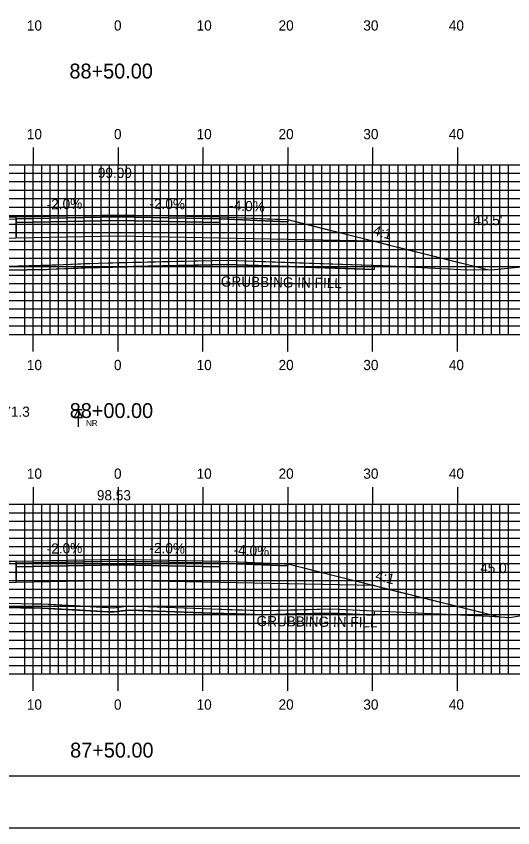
# Model space of a CAD drawing. Extents: x 1764152 to 1764495, y 442591 to 442811.
# Drawn here: x 1764305.8 to 1764364.3, y 442590.5 to 442686.2 of the extents above; entities that cross this region are included whole.
import ezdxf

# ---------------------------------------------------------------- set-up
doc = ezdxf.new("R2010")
doc.units = 0
for name, color, linetype in [('ANNOTATION', 7, 'Continuous'), ('BORDER', 7, 'Continuous'), ('BORING - NO REFUSAL', 7, 'Continuous'), ('D_Roadway_Centerline', 7, 'Continuous'), ('D_Roadway_Centerline_Text', 7, 'Continuous'), ('D_Roadway_Edge_Shoulder', 7, 'Continuous'), ('D_Roadway_Edge_TW', 7, 'Continuous'), ('D_Roadway_Pavement', 7, 'Continuous'), ('D_Roadway_SlopeLines', 7, 'Continuous'), ('D_Roadway_SubGrade', 7, 'Continuous'), ('D_Text_Standard', 7, 'Continuous'), ('GRUBBING IN FILL', 7, 'Continuous'), ('H_V ANNOTATION', 7, 'Continuous'), ('MAJOR', 7, 'Continuous'), ('MINOR', 7, 'Continuous'), ('PLOT BOUNDARY', 7, 'Continuous'), ('S_Roadway_Centerline', 7, 'Continuous')]:
    doc.layers.add(name, color=color, linetype=linetype)

msp = doc.modelspace()

# ---------------------------------------------------------------- linework, layer by layer
at = {"layer": 'BORDER'}
msp.add_lwpolyline([(1764168.232, 442596.665), (1764488.232, 442596.665), (1764488.232, 442806.665), (1764168.232, 442806.665)], close=True, dxfattribs=at)
at = {"layer": 'BORING - NO REFUSAL'}
for p, q in [((1764313.611, 442639.787), (1764312.652, 442639.787)), ((1764313.132, 442638.827), (1764313.132, 442637.768))]:
    msp.add_line(p, q, dxfattribs=at)
msp.add_lwpolyline([(1764313.132, 442639.787), (1764313.611, 442638.827), (1764312.652, 442638.827)], close=True, dxfattribs=at)
at = {"layer": 'D_Roadway_Centerline'}
for points in [[(1764280.078, 442657.758), (1764284.623, 442658.894), (1764287.657, 442659.653), (1764292.966, 442660.981), (1764297.813, 442662.192), (1764297.832, 442662.197), (1764297.847, 442662.198), (1764304.946, 442662.482), (1764305.832, 442662.517), (1764317.826, 442662.757), (1764317.831, 442662.757), (1764329.826, 442662.517), (1764329.832, 442662.517), (1764329.836, 442662.517), (1764336.402, 442662.254), (1764337.832, 442662.197), (1764339.339, 442661.82), (1764348.006, 442659.653), (1764349.62, 442659.25), (1764349.832, 442659.197), (1764351.315, 442658.826), (1764361.371, 442656.312)], [(1764279.768, 442617.12), (1764287.379, 442619.022), (1764287.658, 442619.092), (1764296.589, 442621.326), (1764297.831, 442621.636), (1764305.196, 442621.931), (1764305.832, 442621.956), (1764317.832, 442622.196), (1764329.832, 442621.956), (1764333.031, 442621.828), (1764337.448, 442621.652), (1764337.831, 442621.636), (1764341.569, 442620.702), (1764348.004, 442619.093), (1764348.006, 442619.092), (1764349.264, 442618.778), (1764349.831, 442618.636), (1764349.833, 442618.636), (1764350.364, 442618.503), (1764362.819, 442615.389)]]:
    msp.add_lwpolyline(points, dxfattribs=at)
at = {"layer": 'D_Roadway_Edge_Shoulder'}
for points in [[(1764305.832, 442662.517), (1764297.832, 442662.197), (1764297.832, 442661.947), (1764305.832, 442662.267)], [(1764329.832, 442662.517), (1764337.832, 442662.197), (1764337.832, 442661.947), (1764329.832, 442662.267)], [(1764305.832, 442621.956), (1764297.831, 442621.636), (1764297.831, 442621.386), (1764305.832, 442621.706)], [(1764329.832, 442621.956), (1764337.831, 442621.636), (1764337.831, 442621.386), (1764329.832, 442621.706)]]:
    msp.add_lwpolyline(points, close=True, dxfattribs=at)
at = {"layer": 'D_Roadway_Edge_TW'}
for points in [[(1764305.832, 442662.267), (1764305.832, 442662.517), (1764317.831, 442662.757), (1764329.832, 442662.517), (1764329.832, 442662.267), (1764317.831, 442662.507)], [(1764329.832, 442662.517), (1764329.832, 442662.517), (1764329.832, 442662.267), (1764329.832, 442662.267)], [(1764305.832, 442621.706), (1764305.832, 442621.956), (1764317.832, 442622.196), (1764329.832, 442621.956), (1764329.832, 442621.706), (1764317.832, 442621.946)], [(1764329.832, 442621.956), (1764329.832, 442621.956), (1764329.832, 442621.706), (1764329.832, 442621.706)]]:
    msp.add_lwpolyline(points, close=True, dxfattribs=at)
at = {"layer": 'D_Roadway_Pavement'}
for points in [[(1764305.832, 442661.85), (1764305.832, 442662.267), (1764317.831, 442662.507), (1764329.832, 442662.267), (1764329.832, 442661.85), (1764317.831, 442662.09)], [(1764329.832, 442662.267), (1764329.832, 442662.267), (1764329.832, 442661.85), (1764329.832, 442661.85)], [(1764305.832, 442621.289), (1764305.832, 442621.706), (1764317.832, 442621.946), (1764329.832, 442621.706), (1764329.832, 442621.289), (1764317.832, 442621.529)], [(1764329.832, 442621.706), (1764329.832, 442621.706), (1764329.832, 442621.289), (1764329.832, 442621.289)]]:
    msp.add_lwpolyline(points, close=True, dxfattribs=at)
for points in [[(1764329.832, 442662.267), (1764329.832, 442661.85)], [(1764329.832, 442662.267), (1764329.832, 442661.85)], [(1764329.832, 442662.267), (1764329.832, 442661.85)], [(1764329.832, 442621.706), (1764329.832, 442621.289)], [(1764329.832, 442621.706), (1764329.832, 442621.289)], [(1764329.832, 442621.706), (1764329.832, 442621.289)]]:
    msp.add_lwpolyline(points, dxfattribs=at)
at = {"layer": 'D_Roadway_SlopeLines'}
for points in [[(1764337.832, 442662.197), (1764348.005, 442659.653), (1764349.832, 442659.197), (1764361.371, 442656.312)], [(1764337.831, 442621.636), (1764348.006, 442619.092), (1764349.831, 442618.636), (1764362.819, 442615.389)]]:
    msp.add_lwpolyline(points, dxfattribs=at)
at = {"layer": 'D_Roadway_SubGrade'}
for points in [[(1764297.832, 442661.947), (1764305.832, 442662.267), (1764305.832, 442661.85), (1764305.832, 442660.017), (1764287.657, 442659.653), (1764297.832, 442662.197)], [(1764329.832, 442661.85), (1764329.832, 442662.267), (1764337.832, 442661.947), (1764337.832, 442662.197), (1764348.005, 442659.653), (1764329.832, 442660.017)], [(1764305.832, 442660.017), (1764305.832, 442661.85), (1764317.831, 442662.09), (1764329.832, 442661.85), (1764329.832, 442660.017), (1764317.831, 442660.257)], [(1764329.832, 442661.85), (1764329.832, 442661.85), (1764329.832, 442660.017), (1764329.832, 442660.017)], [(1764297.831, 442621.386), (1764305.832, 442621.706), (1764305.832, 442621.289), (1764305.832, 442619.456), (1764287.658, 442619.092), (1764297.831, 442621.636)], [(1764305.832, 442619.456), (1764305.832, 442621.289), (1764317.832, 442621.529), (1764329.832, 442621.289), (1764329.832, 442619.456), (1764317.832, 442619.696)], [(1764329.832, 442621.289), (1764329.832, 442621.706), (1764337.831, 442621.386), (1764337.831, 442621.636), (1764348.006, 442619.092), (1764329.832, 442619.456)], [(1764329.832, 442621.289), (1764329.832, 442621.289), (1764329.832, 442619.456), (1764329.832, 442619.456)]]:
    msp.add_lwpolyline(points, close=True, dxfattribs=at)
at = {"layer": 'GRUBBING IN FILL'}
for p, q in [((1764348.005, 442656.806), (1764348.005, 442656.301)), ((1764348.006, 442616.095), (1764348.006, 442615.595))]:
    msp.add_line(p, q, dxfattribs=at)
for points in [[(1764315.517, 442657.067), (1764317.832, 442657.121), (1764317.832, 442656.621), (1764315.529, 442656.567), (1764309.549, 442656.325), (1764304.695, 442656.224), (1764300.033, 442656.141), (1764298.141, 442656.207), (1764292.899, 442656.574), (1764287.657, 442656.941), (1764287.657, 442657.431), (1764288.087, 442657.412), (1764298.173, 442656.706), (1764299.591, 442656.645), (1764304.679, 442656.723), (1764311.395, 442656.917)], [(1764315.517, 442657.067), (1764317.832, 442657.121), (1764317.832, 442656.621), (1764315.529, 442656.567), (1764309.549, 442656.325), (1764304.695, 442656.224), (1764300.033, 442656.141), (1764298.141, 442656.207), (1764292.899, 442656.574), (1764287.657, 442656.941), (1764287.657, 442657.431), (1764288.087, 442657.412), (1764298.173, 442656.706), (1764299.591, 442656.645), (1764304.679, 442656.723), (1764311.395, 442656.917)], [(1764317.832, 442657.121), (1764323.083, 442657.244), (1764330.649, 442657.421), (1764339.173, 442657.117), (1764347.696, 442656.812), (1764348.005, 442656.806), (1764348.005, 442656.301), (1764339.326, 442656.611), (1764330.646, 442656.921), (1764323.088, 442656.744), (1764317.832, 442656.621)], [(1764317.832, 442657.121), (1764323.083, 442657.244), (1764330.649, 442657.421), (1764339.173, 442657.117), (1764347.696, 442656.812), (1764348.005, 442656.806), (1764348.005, 442656.301), (1764339.326, 442656.611), (1764330.646, 442656.921), (1764323.088, 442656.744), (1764317.832, 442656.621)], [(1764287.658, 442616.568), (1764287.658, 442617.068), (1764291.507, 442617.073), (1764299.468, 442617.083), (1764306.366, 442616.966), (1764307.832, 442616.943), (1764308.883, 442616.927), (1764312.769, 442616.714), (1764316.654, 442616.502), (1764317.299, 442616.475), (1764317.832, 442616.542), (1764317.832, 442616.038), (1764317.32, 442615.974), (1764316.63, 442616.002), (1764312.748, 442616.215), (1764308.865, 442616.427), (1764307.832, 442616.443), (1764306.353, 442616.467), (1764303.84, 442616.506), (1764299.464, 442616.582), (1764293.561, 442616.575)], [(1764287.658, 442616.568), (1764287.658, 442617.068), (1764291.507, 442617.073), (1764299.468, 442617.083), (1764306.366, 442616.966), (1764307.832, 442616.943), (1764308.883, 442616.927), (1764312.769, 442616.714), (1764316.654, 442616.502), (1764317.299, 442616.475), (1764317.832, 442616.542), (1764317.832, 442616.038), (1764317.32, 442615.974), (1764316.63, 442616.002), (1764312.748, 442616.215), (1764308.865, 442616.427), (1764307.832, 442616.443), (1764306.353, 442616.467), (1764303.84, 442616.506), (1764299.464, 442616.582), (1764293.561, 442616.575)], [(1764317.832, 442616.038), (1764317.832, 442616.542), (1764318.21, 442616.589), (1764319.12, 442616.703), (1764320.786, 442616.643), (1764322.451, 442616.583), (1764325.638, 442616.455), (1764328.825, 442616.326), (1764331.879, 442616.237), (1764334.934, 442616.148), (1764338.92, 442616.238), (1764342.905, 442616.329), (1764348.006, 442616.095), (1764348.006, 442615.595), (1764342.9, 442615.828), (1764338.916, 442615.738), (1764334.932, 442615.647), (1764331.87, 442615.737), (1764328.807, 442615.827), (1764325.62, 442615.955), (1764322.432, 442616.084), (1764320.787, 442616.143), (1764319.142, 442616.202), (1764318.231, 442616.088)], [(1764317.832, 442616.038), (1764317.832, 442616.542), (1764318.21, 442616.589), (1764319.12, 442616.703), (1764320.786, 442616.643), (1764322.451, 442616.583), (1764325.638, 442616.455), (1764328.825, 442616.326), (1764331.879, 442616.237), (1764334.934, 442616.148), (1764338.92, 442616.238), (1764342.905, 442616.329), (1764348.006, 442616.095), (1764348.006, 442615.595), (1764342.9, 442615.828), (1764338.916, 442615.738), (1764334.932, 442615.647), (1764331.87, 442615.737), (1764328.807, 442615.827), (1764325.62, 442615.955), (1764322.432, 442616.084), (1764320.787, 442616.143), (1764319.142, 442616.202), (1764318.231, 442616.088)]]:
    msp.add_lwpolyline(points, close=True, dxfattribs=at)
for points in [[(1764287.657, 442656.941), (1764298.141, 442656.207), (1764299.135, 442656.149), (1764300.033, 442656.141), (1764309.357, 442656.306), (1764309.741, 442656.344), (1764313.105, 442656.491), (1764313.933, 442656.525), (1764315.529, 442656.567), (1764330.646, 442656.921), (1764348.005, 442656.301)], [(1764287.658, 442616.568), (1764299.464, 442616.582), (1764303.84, 442616.506), (1764308.865, 442616.427), (1764316.63, 442616.002), (1764317.32, 442615.974), (1764319.142, 442616.202), (1764322.432, 442616.084), (1764328.807, 442615.827), (1764334.932, 442615.647), (1764342.9, 442615.828), (1764348.006, 442615.595)]]:
    msp.add_lwpolyline(points, dxfattribs=at)
at = {"layer": 'MAJOR'}
for p, q in [((1764307.832, 442670.669), (1764307.832, 442668.665)), ((1764317.832, 442670.669), (1764317.832, 442668.665)), ((1764327.832, 442670.669), (1764327.832, 442668.665)), ((1764337.832, 442670.669), (1764337.832, 442668.665)), ((1764347.832, 442670.669), (1764347.832, 442668.665)), ((1764357.832, 442670.669), (1764357.832, 442668.665)), ((1764177.832, 442668.665), (1764457.832, 442668.665)), ((1764177.832, 442668.665), (1764457.832, 442668.665)), ((1764307.832, 442648.665), (1764307.832, 442668.665)), ((1764317.832, 442648.665), (1764317.832, 442668.665)), ((1764327.832, 442648.665), (1764327.832, 442668.665)), ((1764337.832, 442648.665), (1764337.832, 442668.665)), ((1764347.832, 442648.665), (1764347.832, 442668.665)), ((1764357.832, 442648.665), (1764357.832, 442668.665)), ((1764177.832, 442663.665), (1764457.832, 442663.665)), ((1764177.832, 442658.665), (1764457.832, 442658.665)), ((1764177.832, 442653.665), (1764457.832, 442653.665)), ((1764177.832, 442648.665), (1764457.832, 442648.665)), ((1764177.832, 442648.665), (1764457.832, 442648.665)), ((1764307.832, 442646.661), (1764307.832, 442648.665)), ((1764317.832, 442646.661), (1764317.832, 442648.665)), ((1764327.832, 442646.661), (1764327.832, 442648.665)), ((1764337.832, 442646.661), (1764337.832, 442648.665)), ((1764347.832, 442646.661), (1764347.832, 442648.665)), ((1764357.832, 442646.661), (1764357.832, 442648.665)), ((1764307.832, 442630.669), (1764307.832, 442628.665)), ((1764317.832, 442630.669), (1764317.832, 442628.665)), ((1764327.832, 442630.669), (1764327.832, 442628.665)), ((1764337.832, 442630.669), (1764337.832, 442628.665)), ((1764347.832, 442630.669), (1764347.832, 442628.665)), ((1764357.832, 442630.669), (1764357.832, 442628.665)), ((1764177.832, 442628.665), (1764457.832, 442628.665)), ((1764177.832, 442628.665), (1764457.832, 442628.665)), ((1764307.832, 442608.665), (1764307.832, 442628.665)), ((1764317.832, 442608.665), (1764317.832, 442628.665)), ((1764327.832, 442608.665), (1764327.832, 442628.665)), ((1764337.832, 442608.665), (1764337.832, 442628.665)), ((1764347.832, 442608.665), (1764347.832, 442628.665)), ((1764357.832, 442608.665), (1764357.832, 442628.665)), ((1764177.832, 442623.665), (1764457.832, 442623.665)), ((1764177.832, 442618.665), (1764457.832, 442618.665)), ((1764177.832, 442613.665), (1764457.832, 442613.665)), ((1764177.832, 442608.665), (1764457.832, 442608.665)), ((1764177.832, 442608.665), (1764457.832, 442608.665)), ((1764307.832, 442606.661), (1764307.832, 442608.665)), ((1764317.832, 442606.661), (1764317.832, 442608.665)), ((1764327.832, 442606.661), (1764327.832, 442608.665)), ((1764337.832, 442606.661), (1764337.832, 442608.665)), ((1764347.832, 442606.661), (1764347.832, 442608.665)), ((1764357.832, 442606.661), (1764357.832, 442608.665))]:
    msp.add_line(p, q, dxfattribs=at)
at = {"layer": 'MINOR'}
for p, q in [((1764306.832, 442648.665), (1764306.832, 442668.665)), ((1764308.832, 442648.665), (1764308.832, 442668.665)), ((1764309.832, 442648.665), (1764309.832, 442668.665)), ((1764310.832, 442648.665), (1764310.832, 442668.665)), ((1764311.832, 442648.665), (1764311.832, 442668.665)), ((1764312.832, 442648.665), (1764312.832, 442668.665)), ((1764313.832, 442648.665), (1764313.832, 442668.665)), ((1764314.832, 442648.665), (1764314.832, 442668.665)), ((1764315.832, 442648.665), (1764315.832, 442668.665)), ((1764316.832, 442648.665), (1764316.832, 442668.665)), ((1764318.832, 442648.665), (1764318.832, 442668.665)), ((1764319.832, 442648.665), (1764319.832, 442668.665)), ((1764320.832, 442648.665), (1764320.832, 442668.665)), ((1764321.832, 442648.665), (1764321.832, 442668.665)), ((1764322.832, 442648.665), (1764322.832, 442668.665)), ((1764323.832, 442648.665), (1764323.832, 442668.665)), ((1764324.832, 442648.665), (1764324.832, 442668.665)), ((1764325.832, 442648.665), (1764325.832, 442668.665)), ((1764326.832, 442648.665), (1764326.832, 442668.665)), ((1764328.832, 442648.665), (1764328.832, 442668.665)), ((1764329.832, 442648.665), (1764329.832, 442668.665)), ((1764330.832, 442648.665), (1764330.832, 442668.665)), ((1764331.832, 442648.665), (1764331.832, 442668.665)), ((1764332.832, 442648.665), (1764332.832, 442668.665)), ((1764333.832, 442648.665), (1764333.832, 442668.665)), ((1764334.832, 442648.665), (1764334.832, 442668.665)), ((1764335.832, 442648.665), (1764335.832, 442668.665)), ((1764336.832, 442648.665), (1764336.832, 442668.665)), ((1764338.832, 442648.665), (1764338.832, 442668.665)), ((1764339.832, 442648.665), (1764339.832, 442668.665)), ((1764340.832, 442648.665), (1764340.832, 442668.665)), ((1764341.832, 442648.665), (1764341.832, 442668.665)), ((1764342.832, 442648.665), (1764342.832, 442668.665)), ((1764343.832, 442648.665), (1764343.832, 442668.665)), ((1764344.832, 442648.665), (1764344.832, 442668.665)), ((1764345.832, 442648.665), (1764345.832, 442668.665)), ((1764346.832, 442648.665), (1764346.832, 442668.665)), ((1764348.832, 442648.665), (1764348.832, 442668.665)), ((1764349.832, 442648.665), (1764349.832, 442668.665)), ((1764350.832, 442648.665), (1764350.832, 442668.665)), ((1764351.832, 442648.665), (1764351.832, 442668.665)), ((1764352.832, 442648.665), (1764352.832, 442668.665)), ((1764353.832, 442648.665), (1764353.832, 442668.665)), ((1764354.832, 442648.665), (1764354.832, 442668.665)), ((1764355.832, 442648.665), (1764355.832, 442668.665)), ((1764356.832, 442648.665), (1764356.832, 442668.665)), ((1764358.832, 442648.665), (1764358.832, 442668.665)), ((1764359.832, 442648.665), (1764359.832, 442668.665)), ((1764360.832, 442648.665), (1764360.832, 442668.665)), ((1764361.832, 442648.665), (1764361.832, 442668.665)), ((1764362.832, 442648.665), (1764362.832, 442668.665)), ((1764363.832, 442648.665), (1764363.832, 442668.665)), ((1764177.832, 442667.665), (1764457.832, 442667.665)), ((1764177.832, 442666.665), (1764457.832, 442666.665)), ((1764177.832, 442665.665), (1764457.832, 442665.665)), ((1764177.832, 442664.665), (1764457.832, 442664.665)), ((1764177.832, 442662.665), (1764457.832, 442662.665)), ((1764177.832, 442661.665), (1764457.832, 442661.665)), ((1764177.832, 442660.665), (1764457.832, 442660.665)), ((1764177.832, 442659.665), (1764457.832, 442659.665)), ((1764177.832, 442657.665), (1764457.832, 442657.665)), ((1764177.832, 442656.665), (1764457.832, 442656.665)), ((1764177.832, 442655.665), (1764457.832, 442655.665)), ((1764177.832, 442654.665), (1764457.832, 442654.665)), ((1764177.832, 442652.665), (1764457.832, 442652.665)), ((1764177.832, 442651.665), (1764457.832, 442651.665)), ((1764177.832, 442650.665), (1764457.832, 442650.665)), ((1764177.832, 442649.665), (1764457.832, 442649.665)), ((1764306.832, 442608.665), (1764306.832, 442628.665)), ((1764308.832, 442608.665), (1764308.832, 442628.665)), ((1764309.832, 442608.665), (1764309.832, 442628.665)), ((1764310.832, 442608.665), (1764310.832, 442628.665)), ((1764311.832, 442608.665), (1764311.832, 442628.665)), ((1764312.832, 442608.665), (1764312.832, 442628.665)), ((1764313.832, 442608.665), (1764313.832, 442628.665)), ((1764314.832, 442608.665), (1764314.832, 442628.665)), ((1764315.832, 442608.665), (1764315.832, 442628.665)), ((1764316.832, 442608.665), (1764316.832, 442628.665)), ((1764318.832, 442608.665), (1764318.832, 442628.665)), ((1764319.832, 442608.665), (1764319.832, 442628.665)), ((1764320.832, 442608.665), (1764320.832, 442628.665)), ((1764321.832, 442608.665), (1764321.832, 442628.665)), ((1764322.832, 442608.665), (1764322.832, 442628.665)), ((1764323.832, 442608.665), (1764323.832, 442628.665)), ((1764324.832, 442608.665), (1764324.832, 442628.665)), ((1764325.832, 442608.665), (1764325.832, 442628.665)), ((1764326.832, 442608.665), (1764326.832, 442628.665)), ((1764328.832, 442608.665), (1764328.832, 442628.665)), ((1764329.832, 442608.665), (1764329.832, 442628.665)), ((1764330.832, 442608.665), (1764330.832, 442628.665)), ((1764331.832, 442608.665), (1764331.832, 442628.665)), ((1764332.832, 442608.665), (1764332.832, 442628.665)), ((1764333.832, 442608.665), (1764333.832, 442628.665)), ((1764334.832, 442608.665), (1764334.832, 442628.665)), ((1764335.832, 442608.665), (1764335.832, 442628.665)), ((1764336.832, 442608.665), (1764336.832, 442628.665)), ((1764338.832, 442608.665), (1764338.832, 442628.665)), ((1764339.832, 442608.665), (1764339.832, 442628.665)), ((1764340.832, 442608.665), (1764340.832, 442628.665)), ((1764341.832, 442608.665), (1764341.832, 442628.665)), ((1764342.832, 442608.665), (1764342.832, 442628.665)), ((1764343.832, 442608.665), (1764343.832, 442628.665)), ((1764344.832, 442608.665), (1764344.832, 442628.665)), ((1764345.832, 442608.665), (1764345.832, 442628.665)), ((1764346.832, 442608.665), (1764346.832, 442628.665)), ((1764348.832, 442608.665), (1764348.832, 442628.665)), ((1764349.832, 442608.665), (1764349.832, 442628.665)), ((1764350.832, 442608.665), (1764350.832, 442628.665)), ((1764351.832, 442608.665), (1764351.832, 442628.665)), ((1764352.832, 442608.665), (1764352.832, 442628.665)), ((1764353.832, 442608.665), (1764353.832, 442628.665)), ((1764354.832, 442608.665), (1764354.832, 442628.665)), ((1764355.832, 442608.665), (1764355.832, 442628.665)), ((1764356.832, 442608.665), (1764356.832, 442628.665)), ((1764358.832, 442608.665), (1764358.832, 442628.665)), ((1764359.832, 442608.665), (1764359.832, 442628.665)), ((1764360.832, 442608.665), (1764360.832, 442628.665)), ((1764361.832, 442608.665), (1764361.832, 442628.665)), ((1764362.832, 442608.665), (1764362.832, 442628.665)), ((1764363.832, 442608.665), (1764363.832, 442628.665)), ((1764177.832, 442627.665), (1764457.832, 442627.665)), ((1764177.832, 442626.665), (1764457.832, 442626.665)), ((1764177.832, 442625.665), (1764457.832, 442625.665)), ((1764177.832, 442624.665), (1764457.832, 442624.665)), ((1764177.832, 442622.665), (1764457.832, 442622.665)), ((1764177.832, 442621.665), (1764457.832, 442621.665)), ((1764177.832, 442620.665), (1764457.832, 442620.665)), ((1764177.832, 442619.665), (1764457.832, 442619.665)), ((1764177.832, 442617.665), (1764457.832, 442617.665)), ((1764177.832, 442616.665), (1764457.832, 442616.665)), ((1764177.832, 442615.665), (1764457.832, 442615.665)), ((1764177.832, 442614.665), (1764457.832, 442614.665)), ((1764177.832, 442612.665), (1764457.832, 442612.665)), ((1764177.832, 442611.665), (1764457.832, 442611.665)), ((1764177.832, 442610.665), (1764457.832, 442610.665)), ((1764177.832, 442609.665), (1764457.832, 442609.665))]:
    msp.add_line(p, q, dxfattribs=at)
at = {"layer": 'PLOT BOUNDARY'}
msp.add_lwpolyline([(1764152.045, 442590.547), (1764492.045, 442590.547), (1764492.045, 442810.547), (1764152.045, 442810.547)], close=True, dxfattribs=at)
at = {"layer": 'S_Roadway_Centerline'}
for points in [[(1764251.278, 442657.549), (1764259.854, 442657.646), (1764263.196, 442657.753), (1764268.944, 442657.824), (1764277.66, 442657.863), (1764288.087, 442657.412), (1764298.173, 442656.706), (1764299.151, 442656.648), (1764300.031, 442656.641), (1764309.327, 442656.806), (1764309.705, 442656.843), (1764313.084, 442656.991), (1764313.916, 442657.025), (1764315.517, 442657.067), (1764330.649, 442657.421), (1764347.696, 442656.812), (1764348.703, 442656.8), (1764349.029, 442656.775), (1764358.973, 442656.27), (1764362.202, 442656.327), (1764366.149, 442656.697)], [(1764251.625, 442617.494), (1764263.457, 442617.607), (1764267.585, 442617.666), (1764279.171, 442617.138), (1764281.746, 442617.058), (1764283.546, 442617.063), (1764299.468, 442617.083), (1764303.849, 442617.006), (1764308.883, 442616.927), (1764316.654, 442616.502), (1764317.299, 442616.475), (1764319.12, 442616.703), (1764322.451, 442616.583), (1764328.825, 442616.326), (1764334.934, 442616.148), (1764342.905, 442616.329), (1764361.604, 442615.473), (1764363.987, 442615.308), (1764366.022, 442615.67)]]:
    msp.add_lwpolyline(points, dxfattribs=at)

# ---------------------------------------------------------------- texts
at = {"layer": 'ANNOTATION'}
for s, rotation, p in [('-2.0%', 1.14585, (1764309.435, 442663.39)), ('-2.0%', 358.85429, (1764321.515, 442663.484)), ('-4.0%', 357.70931, (1764330.91, 442663.276)), ('4:1', 345.96109, (1764347.777, 442660.373)), ('-2.0%', 1.14574, (1764309.438, 442622.829)), ('-2.0%', 358.85426, (1764321.518, 442622.923)), ('-4.0%', 357.70909, (1764331.432, 442622.694)), ('4:1', 345.96231, (1764348.069, 442619.756))]:
    msp.add_text(s, height=1.2, rotation=rotation, dxfattribs=at).set_placement(p)
at = {"layer": 'BORING - NO REFUSAL'}
msp.add_text('APPROX. ELEV.  71.3', height=1.2, rotation=359.81416, dxfattribs=at).set_placement((1764291.288, 442639.015))
msp.add_text('NR', height=0.6998, dxfattribs=at).set_placement((1764314.064, 442637.871))
at = {"layer": 'D_Roadway_Centerline'}
for s, p in [('C', (1764317.826, 442662.757)), ('L', (1764317.831, 442662.75)), ('C', (1764317.827, 442622.196)), ('L', (1764317.832, 442622.189))]:
    msp.add_text(s, height=0.0146, dxfattribs=at).set_placement(p)
at = {"layer": 'D_Roadway_Centerline_Text'}
for s, p in [('99.09', (1764315.445, 442667.107)), ('98.53', (1764315.333, 442629.119))]:
    msp.add_text(s, height=1.2, dxfattribs=at).set_placement(p)
at = {"layer": 'D_Text_Standard'}
for s, p in [("43.5'", (1764359.695, 442661.529)), ("45.0'", (1764360.502, 442620.55))]:
    msp.add_text(s, height=1.2, dxfattribs=at).set_placement(p)
at = {"layer": 'GRUBBING IN FILL'}
for rotation, p in [(359.19507, (1764329.935, 442654.312)), (359.35531, (1764334.141, 442614.308))]:
    msp.add_text('GRUBBING IN FILL', height=1.2, rotation=rotation, dxfattribs=at).set_placement(p)
at = {"layer": 'H_V ANNOTATION'}
for s, height, p in [('10', 1.2, (1764307.082, 442684.465)), ('0', 1.2, (1764317.35, 442684.465)), ('10', 1.2, (1764327.082, 442684.465)), ('20', 1.2, (1764336.74, 442684.465)), ('30', 1.2, (1764346.729, 442684.465)), ('40', 1.2, (1764356.804, 442684.465)), ('88+50.00', 1.75, (1764312.104, 442678.821)), ('10', 1.2, (1764307.082, 442671.665)), ('0', 1.2, (1764317.35, 442671.665)), ('10', 1.2, (1764327.082, 442671.665)), ('20', 1.2, (1764336.74, 442671.665)), ('30', 1.2, (1764346.729, 442671.665)), ('40', 1.2, (1764356.804, 442671.665)), ('10', 1.2, (1764307.082, 442644.465)), ('0', 1.2, (1764317.35, 442644.465)), ('10', 1.2, (1764327.082, 442644.465)), ('20', 1.2, (1764336.74, 442644.465)), ('30', 1.2, (1764346.729, 442644.465)), ('40', 1.2, (1764356.804, 442644.465)), ('88+00.00', 1.75, (1764312.135, 442638.821)), ('10', 1.2, (1764307.082, 442631.665)), ('0', 1.2, (1764317.35, 442631.665)), ('10', 1.2, (1764327.082, 442631.665)), ('20', 1.2, (1764336.74, 442631.665)), ('30', 1.2, (1764346.729, 442631.665)), ('40', 1.2, (1764356.804, 442631.665)), ('10', 1.2, (1764307.082, 442604.465)), ('0', 1.2, (1764317.35, 442604.465)), ('10', 1.2, (1764327.082, 442604.465)), ('20', 1.2, (1764336.74, 442604.465)), ('30', 1.2, (1764346.729, 442604.465)), ('40', 1.2, (1764356.804, 442604.465)), ('87+50.00', 1.75, (1764312.182, 442598.821))]:
    msp.add_text(s, height=height, dxfattribs=at).set_placement(p)

doc.saveas('drawing.dxf')
